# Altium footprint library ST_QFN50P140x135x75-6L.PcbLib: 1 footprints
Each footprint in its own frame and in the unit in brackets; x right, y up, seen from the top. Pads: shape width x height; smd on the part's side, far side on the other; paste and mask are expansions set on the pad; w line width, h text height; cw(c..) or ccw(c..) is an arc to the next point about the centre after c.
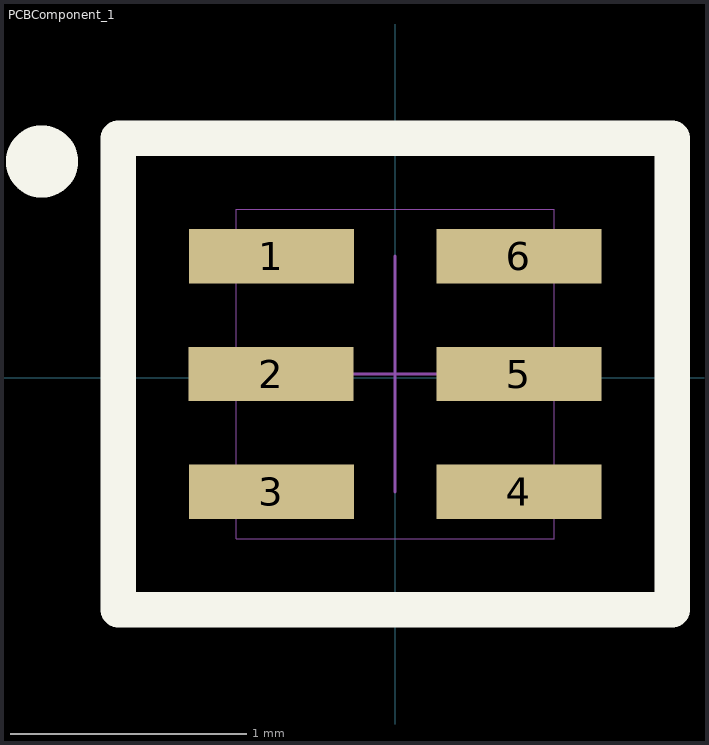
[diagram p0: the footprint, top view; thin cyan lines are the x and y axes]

## PCBComponent_1 [mm]
pads (6):
  rect 0.7x0.23 smd paste-20 mask+0.05: 1(-0.524,0.516) 2(-0.525,0.016) 3(-0.524,-0.484) 4(0.526,-0.484) 5(0.526,0.016) 6(0.526,0.516)
Top Overlay:
  circle w0.254: c-1.498,0.917 r0.026
  lines w0.15: -1.174,-0.984 1.176,-0.984 1.176,1.016 -1.174,1.016 -1.174,-0.984
Top Paste:
  rectangle: 0.194,0.407 0.858,0.625
  rectangle: 0.194,-0.093 0.858,0.125
  rectangle: 0.194,-0.593 0.858,-0.375
  rectangle: -0.856,-0.593 -0.192,-0.375
  rectangle: -0.856,0.407 -0.192,0.625
  rectangle: -0.856,-0.093 -0.192,0.125
Mechanical 1:
  lines w0: -0.674,-0.684 0.676,-0.684 0.676,0.716 -0.674,0.716 -0.674,-0.684
  lines w0.013: -0.499,0.016 0.501,0.016 ; 0.001,-0.484 0.001,0.516
3D body "ST_DFN_140x135x80_6L_WF.STEP": height 0.81, standoff 0.01, extent -0.674,-0.684 0.676,0.716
